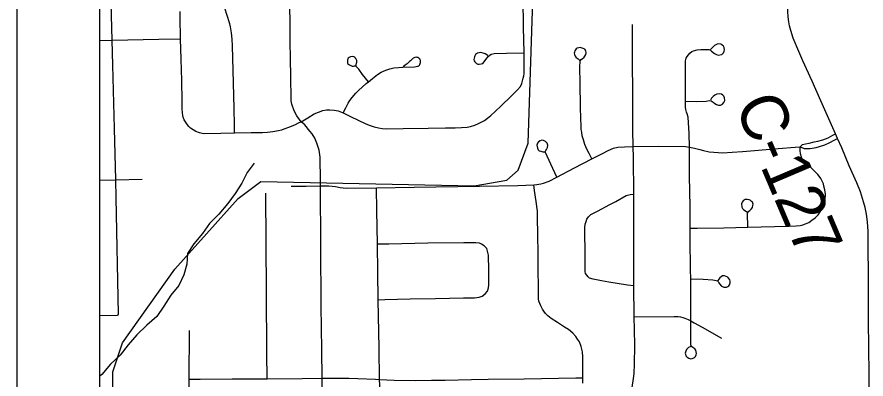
# Model space of a CAD drawing. Extents: x 0 to 34, y -5 to 22.
# Drawn here: x 2 to 3.028, y 19.297 to 19.735 of the extents above; entities that cross this region are included whole.
import ezdxf

# ---------------------------------------------------------------- set-up
doc = ezdxf.new("R2010")
doc.units = 0
for name, color, linetype in [('GM_X_City_Street', 7, 'Continuous'), ('GM_X_County_Road', 7, 'Continuous'), ('GM_X_County_Road_Text', 7, 'Continuous'), ('GM_X_Minor_River', 7, 'Continuous'), ('GM_X_Rail_Line', 7, 'Continuous'), ('GM_X_US_Route', 7, 'Continuous'), ('SH_Cut_Line', 7, 'Continuous'), ('SH_Data', 7, 'Continuous')]:
    doc.layers.add(name, color=color, linetype=linetype)

msp = doc.modelspace()

# ---------------------------------------------------------------- linework, layer by layer
at = {"layer": 'GM_X_City_Street'}
for points in [[(2.1227, 19.3747), (2.1231, 19.3759), (2.1202, 19.5161), (2.1196, 19.538), (2.1181, 19.6002), (2.1159, 19.6767), (2.1154, 19.7071), (2.1136, 19.7672), (2.1134, 19.7782), (2.1131, 19.7867), (2.1134, 19.7899), (2.1141, 19.7918), (2.1152, 19.7943), (2.1159, 19.7953), (2.1174, 19.7975), (2.1194, 19.7995), (2.1242, 19.8024), (2.1323, 19.8068), (2.1497, 19.8166), (2.1761, 19.8318), (2.1865, 19.8378)], [(2.2633, 19.5944), (2.2632, 19.6037), (2.2629, 19.6249), (2.2617, 19.6702), (2.2609, 19.7003), (2.2606, 19.7083), (2.2599, 19.7159), (2.2585, 19.7231), (2.2579, 19.7269), (2.2543, 19.7379), (2.2519, 19.7447), (2.2489, 19.7513), (2.245, 19.7588), (2.2427, 19.7622), (2.2401, 19.7664), (2.2343, 19.7743), (2.2273, 19.7834), (2.2232, 19.7885)], [(2.3698, 19.2697), (2.3695, 19.2977), (2.3692, 19.3323), (2.3685, 19.3853), (2.3676, 19.5307), (2.3674, 19.5367), (2.3671, 19.5654), (2.3659, 19.574), (2.3632, 19.5822), (2.3608, 19.5883), (2.3574, 19.5937), (2.3548, 19.5969), (2.3484, 19.6044), (2.344, 19.6083), (2.3388, 19.6153), (2.3356, 19.6213), (2.3329, 19.6295), (2.3322, 19.6336), (2.3319, 19.6376), (2.3316, 19.6609), (2.3313, 19.6864), (2.331, 19.7035), (2.3307, 19.7276), (2.3301, 19.7693)], [(2.344, 19.6083), (2.3432, 19.6078), (2.3405, 19.6064), (2.337, 19.6047), (2.3302, 19.6017), (2.3232, 19.5991), (2.3203, 19.5982), (2.3165, 19.5973), (2.3099, 19.5962), (2.3034, 19.5954), (2.2973, 19.595), (2.2834, 19.5948), (2.2633, 19.5944), (2.2467, 19.594), (2.2276, 19.5937), (2.2244, 19.5941), (2.221, 19.5948), (2.2166, 19.5964), (2.2133, 19.5983), (2.2101, 19.6007), (2.208, 19.6027), (2.2065, 19.6046), (2.2041, 19.608), (2.2026, 19.6106), (2.2013, 19.6139), (2.2007, 19.6159), (2.2003, 19.6189), (2.2002, 19.624), (2.1999, 19.6332), (2.1995, 19.6582), (2.1989, 19.6841), (2.1982, 19.7088), (2.1975, 19.7346), (2.1978, 19.7417)], [(2.344, 19.6083), (2.3523, 19.613), (2.3597, 19.6178), (2.365, 19.62), (2.3702, 19.6218), (2.375, 19.6225), (2.3789, 19.6228), (2.3839, 19.6223), (2.3891, 19.6213), (2.3951, 19.6189), (2.4039, 19.6148), (2.4223, 19.6059), (2.4278, 19.6036), (2.4324, 19.602), (2.4379, 19.6008), (2.4423, 19.6), (2.4474, 19.5998), (2.4677, 19.6001), (2.4981, 19.6006), (2.519, 19.6009), (2.5306, 19.6011), (2.5384, 19.6013), (2.5452, 19.6017), (2.5491, 19.6027), (2.5543, 19.6042), (2.559, 19.6061), (2.5631, 19.6081), (2.5663, 19.6099), (2.5698, 19.6125), (2.5737, 19.616), (2.5789, 19.6205), (2.5867, 19.628), (2.5979, 19.6388), (2.606, 19.6469), (2.6096, 19.6511), (2.6112, 19.6546), (2.6131, 19.6609), (2.6139, 19.6639), (2.6141, 19.6661), (2.6143, 19.6797), (2.6141, 19.6917), (2.6135, 19.7227), (2.6132, 19.7331), (2.613, 19.7468)], [(2.743, 19.0912), (2.7429, 19.1033), (2.7425, 19.1675), (2.7422, 19.2036), (2.742, 19.2373), (2.742, 19.2436), (2.7422, 19.2495), (2.7422, 19.2602), (2.7424, 19.2677), (2.7431, 19.2752), (2.7448, 19.2864), (2.7464, 19.2976), (2.7472, 19.3037), (2.7477, 19.3147), (2.7481, 19.3376), (2.7478, 19.3566), (2.7473, 19.3723), (2.747, 19.4098), (2.7468, 19.5125), (2.7469, 19.5207), (2.7466, 19.565), (2.7461, 19.5782), (2.7459, 19.5982), (2.7454, 19.7258)], [(2.1, 19.7068), (2.1154, 19.7071), (2.1719, 19.7083), (2.1982, 19.7088)], [(2.8158, 19.3364), (2.8132, 19.3349), (2.8121, 19.3338), (2.8108, 19.3324), (2.8098, 19.3305), (2.8093, 19.3282), (2.8094, 19.3268), (2.81, 19.325), (2.8114, 19.3233), (2.8134, 19.3221), (2.8159, 19.3214), (2.8176, 19.3216), (2.819, 19.3221), (2.8206, 19.323), (2.8217, 19.3243), (2.8224, 19.326), (2.8228, 19.3279), (2.8226, 19.3298), (2.8221, 19.3316), (2.821, 19.3332), (2.8197, 19.3342), (2.8183, 19.3352), (2.8168, 19.3363), (2.8162, 19.3371), (2.8159, 19.3382), (2.816, 19.3432), (2.8161, 19.3473), (2.8161, 19.3579), (2.816, 19.3672), (2.8158, 19.418), (2.8155, 19.4295), (2.8153, 19.4664), (2.8152, 19.4795), (2.815, 19.5051), (2.8144, 19.5428), (2.8142, 19.5776), (2.8139, 19.5941), (2.8129, 19.6137), (2.8114, 19.6178), (2.8108, 19.6199), (2.8099, 19.6229), (2.8095, 19.6259), (2.8095, 19.633), (2.8094, 19.6729), (2.8095, 19.6822), (2.8104, 19.6854), (2.8114, 19.6873), (2.8131, 19.6894), (2.8147, 19.6912), (2.8173, 19.6933), (2.8192, 19.6943), (2.8236, 19.6954), (2.8282, 19.6956), (2.8378, 19.6956), (2.8397, 19.6949), (2.8411, 19.6938), (2.8445, 19.691), (2.8469, 19.6897), (2.8491, 19.6888), (2.8535, 19.6896), (2.8555, 19.6917), (2.8565, 19.6936), (2.8566, 19.6955), (2.8564, 19.698), (2.8554, 19.6997), (2.8536, 19.7014), (2.8522, 19.7022), (2.8498, 19.7027), (2.8478, 19.7023), (2.8461, 19.7015), (2.8446, 19.7005), (2.8435, 19.6995), (2.8418, 19.6978), (2.84, 19.6956)], [(2.57, 19.6883), (2.5668, 19.6903), (2.5644, 19.6912), (2.5616, 19.6919), (2.5578, 19.6913), (2.5563, 19.6905), (2.5553, 19.6895), (2.5545, 19.6881), (2.554, 19.6869), (2.5535, 19.6854), (2.5533, 19.6837), (2.5537, 19.6821), (2.5545, 19.6809), (2.5555, 19.6796), (2.5563, 19.6786), (2.5582, 19.6781), (2.5598, 19.6778), (2.5622, 19.6782), (2.564, 19.6789), (2.5657, 19.6806), (2.5678, 19.6836), (2.5709, 19.6878), (2.5742, 19.6899), (2.5778, 19.6908), (2.5926, 19.6913), (2.6141, 19.6917)], [(2.696, 19.5632), (2.6927, 19.5697), (2.6901, 19.575), (2.6877, 19.5806), (2.686, 19.5862), (2.6846, 19.5912), (2.6838, 19.5956), (2.6833, 19.599), (2.683, 19.6035), (2.6826, 19.6124), (2.6823, 19.626), (2.682, 19.6552), (2.6817, 19.6739), (2.6819, 19.6822), (2.6833, 19.6836), (2.6849, 19.6847), (2.6863, 19.6858), (2.6878, 19.6878), (2.6887, 19.6898), (2.6891, 19.6915), (2.6887, 19.694), (2.6883, 19.6948), (2.6877, 19.696), (2.6858, 19.6971), (2.683, 19.6979), (2.6818, 19.6981), (2.6802, 19.6979), (2.6784, 19.6972), (2.6773, 19.6965), (2.6763, 19.6954), (2.6755, 19.6941), (2.675, 19.6926), (2.6747, 19.6913), (2.675, 19.6896), (2.6754, 19.6886), (2.6759, 19.6876), (2.6766, 19.6866), (2.6773, 19.6859), (2.6782, 19.6852), (2.6794, 19.6843), (2.6815, 19.6826)], [(2.3951, 19.6189), (2.3982, 19.6253), (2.401, 19.6308), (2.403, 19.6339), (2.4057, 19.6377), (2.4103, 19.643), (2.4134, 19.6462), (2.4229, 19.6544), (2.4258, 19.6566), (2.4307, 19.6606), (2.4365, 19.6653), (2.4411, 19.6682), (2.4465, 19.6708), (2.4513, 19.6725), (2.4564, 19.6736), (2.462, 19.674), (2.4673, 19.6742), (2.4815, 19.6748), (2.4833, 19.675), (2.4851, 19.6754), (2.4859, 19.6757), (2.4866, 19.6761), (2.4871, 19.6764), (2.4874, 19.6768), (2.4877, 19.6774), (2.4884, 19.6786), (2.4887, 19.6799), (2.4888, 19.6813), (2.4887, 19.6823), (2.4884, 19.6832), (2.4881, 19.6839), (2.4875, 19.6846), (2.4866, 19.6854), (2.4855, 19.686), (2.4845, 19.6862), (2.4833, 19.6864), (2.4818, 19.6862), (2.4809, 19.6858), (2.4799, 19.6852), (2.4789, 19.6843), (2.4781, 19.6835), (2.4767, 19.6822), (2.4753, 19.681), (2.4741, 19.6799), (2.4725, 19.6785), (2.47, 19.6766), (2.4677, 19.6747)], [(2.4258, 19.6566), (2.4186, 19.6656), (2.4138, 19.6719), (2.4112, 19.6748), (2.4107, 19.676), (2.4108, 19.677), (2.4111, 19.6791), (2.4114, 19.6804), (2.4114, 19.6823), (2.4111, 19.6831), (2.4109, 19.6837), (2.4105, 19.6849), (2.4092, 19.6862), (2.408, 19.6868), (2.4067, 19.6873), (2.4037, 19.687), (2.4021, 19.6862), (2.4011, 19.6852), (2.4005, 19.6842), (2.4003, 19.6832), (2.4002, 19.6823), (2.4001, 19.6815), (2.4003, 19.6795), (2.4008, 19.6785), (2.4017, 19.6776), (2.4028, 19.677), (2.4041, 19.6763), (2.4059, 19.6757), (2.4074, 19.6757), (2.4087, 19.6758), (2.4103, 19.676)], [(2.8095, 19.633), (2.8231, 19.6328), (2.8345, 19.6332), (2.8381, 19.634), (2.8405, 19.6335), (2.8429, 19.632), (2.845, 19.6305), (2.847, 19.6291), (2.8494, 19.6283), (2.852, 19.6285), (2.8544, 19.6295), (2.8561, 19.6316), (2.857, 19.634), (2.8567, 19.6374), (2.8559, 19.6391), (2.8546, 19.6406), (2.8531, 19.6415), (2.8508, 19.642), (2.8473, 19.6415), (2.8452, 19.6405), (2.8429, 19.6388), (2.841, 19.6368), (2.8398, 19.6344)], [(2.6536, 19.541), (2.6489, 19.5518), (2.6419, 19.5665), (2.6397, 19.5718), (2.6403, 19.5733), (2.6413, 19.5746), (2.6424, 19.577), (2.643, 19.58), (2.642, 19.5825), (2.64, 19.5844), (2.6376, 19.5854), (2.6357, 19.5858), (2.6337, 19.5853), (2.6317, 19.5839), (2.6304, 19.5822), (2.6297, 19.58), (2.6302, 19.5761), (2.6312, 19.5741), (2.6325, 19.5732), (2.6343, 19.5725), (2.6366, 19.572), (2.6391, 19.5718)], [(2.9482, 19.5781), (2.9513, 19.5806), (2.9547, 19.5816), (2.9594, 19.5824), (2.9655, 19.5838), (2.9696, 19.5848), (2.976, 19.5865), (2.9822, 19.5889), (2.9879, 19.592), (2.9913, 19.5938)], [(2.9482, 19.5781), (2.9533, 19.576), (2.9563, 19.5757), (2.9606, 19.576), (2.9677, 19.5772), (2.9718, 19.5782), (2.9781, 19.5805), (2.9834, 19.5827), (2.9903, 19.5864), (2.9937, 19.588)], [(2.332, 19.5301), (2.3503, 19.5304), (2.3676, 19.5307), (2.3776, 19.5308), (2.3856, 19.53), (2.3915, 19.5286), (2.3986, 19.5279), (2.4353, 19.5282), (2.4811, 19.529), (2.5601, 19.5304), (2.6065, 19.5312), (2.6259, 19.5319), (2.6296, 19.5323), (2.6343, 19.5332), (2.6375, 19.5339), (2.6446, 19.5364), (2.6536, 19.541), (2.6752, 19.5525), (2.696, 19.5632), (2.7089, 19.5699), (2.716, 19.5735), (2.7224, 19.5762), (2.7276, 19.5773), (2.7356, 19.5781), (2.7461, 19.5782), (2.7768, 19.5786), (2.8096, 19.5783), (2.8142, 19.5776), (2.8203, 19.5764), (2.8269, 19.5747), (2.8314, 19.5736), (2.8381, 19.572), (2.844, 19.5714), (2.8542, 19.5708), (2.8662, 19.5714), (2.8786, 19.5722), (2.9218, 19.5759), (2.9424, 19.5776), (2.9482, 19.5781)], [(2.8152, 19.4795), (2.8237, 19.4796), (2.8561, 19.4798), (2.8849, 19.4806), (2.9173, 19.4814), (2.9352, 19.4818), (2.9436, 19.4822), (2.9485, 19.4828), (2.9515, 19.4836), (2.955, 19.4848), (2.9587, 19.4864), (2.9626, 19.489), (2.9667, 19.4921), (2.97, 19.4955), (2.9727, 19.4992), (2.9753, 19.5037), (2.9763, 19.5069), (2.9774, 19.5108), (2.9781, 19.5135), (2.9786, 19.5157), (2.9789, 19.5181), (2.9789, 19.5207), (2.9784, 19.5257), (2.9772, 19.5302), (2.9765, 19.5331), (2.975, 19.5365), (2.9733, 19.5394), (2.9725, 19.5406), (2.9699, 19.5444), (2.9665, 19.5478), (2.9626, 19.5515), (2.959, 19.5549), (2.9555, 19.5582), (2.9538, 19.5601), (2.9514, 19.5626), (2.95, 19.5655), (2.9489, 19.5693), (2.9482, 19.5734), (2.9482, 19.5781)], [(2.1, 19.5377), (2.1196, 19.538), (2.1516, 19.5386)], [(2.4429, 19.0853), (2.4413, 19.1791), (2.4403, 19.2379), (2.4396, 19.2825), (2.439, 19.2963), (2.4385, 19.3342), (2.4375, 19.3929), (2.4369, 19.4262), (2.4364, 19.4599), (2.4358, 19.5007), (2.4353, 19.5282)], [(2.6854, 19.2919), (2.6854, 19.2982), (2.6852, 19.3239), (2.6849, 19.3299), (2.6832, 19.3364), (2.681, 19.3418), (2.6789, 19.3452), (2.6766, 19.3485), (2.673, 19.3525), (2.6677, 19.3566), (2.6631, 19.3597), (2.6547, 19.3652), (2.647, 19.3703), (2.6429, 19.3733), (2.6399, 19.3763), (2.6378, 19.3791), (2.6363, 19.3813), (2.6343, 19.3854), (2.6331, 19.3883), (2.6321, 19.3912), (2.6315, 19.394), (2.6314, 19.409), (2.6313, 19.4281), (2.6311, 19.4494), (2.6309, 19.4707), (2.6305, 19.4934), (2.6302, 19.5002), (2.6287, 19.5117), (2.6267, 19.5252), (2.6259, 19.5319)], [(2.3029, 19.2972), (2.3026, 19.3283), (2.3021, 19.4021), (2.3012, 19.5217)], [(2.747, 19.4098), (2.7391, 19.4104), (2.7167, 19.4142), (2.7079, 19.4157), (2.6978, 19.4176), (2.6934, 19.4188), (2.6918, 19.4204), (2.6899, 19.4224), (2.6886, 19.4246), (2.688, 19.4268), (2.6879, 19.4547), (2.6878, 19.4699), (2.6877, 19.4799), (2.688, 19.4841), (2.6891, 19.4877), (2.6902, 19.4903), (2.6921, 19.493), (2.6949, 19.4959), (2.7029, 19.5), (2.718, 19.508), (2.725, 19.5116), (2.7378, 19.5188), (2.7425, 19.5204), (2.7469, 19.5207)], [(2.8849, 19.4806), (2.8847, 19.4973), (2.8852, 19.4986), (2.8862, 19.5), (2.8875, 19.501), (2.8892, 19.5026), (2.8907, 19.5043), (2.8912, 19.5067), (2.8913, 19.5084), (2.8905, 19.5108), (2.8895, 19.5119), (2.8878, 19.5132), (2.8865, 19.5137), (2.8844, 19.5142), (2.8819, 19.5141), (2.8805, 19.5134), (2.8792, 19.5124), (2.8783, 19.5108), (2.8774, 19.5091), (2.8777, 19.505), (2.8786, 19.5032), (2.8797, 19.502), (2.8812, 19.5008), (2.8846, 19.4988)], [(2.4375, 19.3929), (2.4456, 19.3931), (2.4761, 19.3941), (2.5066, 19.3944), (2.5409, 19.395), (2.5542, 19.3952), (2.5596, 19.3958), (2.5635, 19.3972), (2.5669, 19.3999), (2.5697, 19.4031), (2.5711, 19.4074), (2.5714, 19.4109), (2.5712, 19.4285), (2.5709, 19.4469), (2.5688, 19.4549), (2.5659, 19.458), (2.5624, 19.4601), (2.5599, 19.4612), (2.5556, 19.4616), (2.541, 19.4615), (2.4976, 19.4611), (2.4501, 19.4602), (2.4364, 19.4599)], [(2.8158, 19.418), (2.8309, 19.4179), (2.8426, 19.4168), (2.8468, 19.4162), (2.8483, 19.4159), (2.8491, 19.4148), (2.85, 19.4134), (2.8507, 19.4119), (2.853, 19.4094), (2.8561, 19.4079), (2.859, 19.408), (2.8608, 19.4088), (2.8622, 19.4098), (2.8629, 19.4109), (2.8636, 19.4133), (2.8636, 19.4153), (2.8631, 19.4169), (2.8622, 19.4186), (2.8606, 19.4201), (2.8589, 19.421), (2.8566, 19.4217), (2.8542, 19.4216), (2.8527, 19.4207), (2.8512, 19.4193), (2.8487, 19.4163)], [(2.1, 19.3739), (2.1218, 19.3742), (2.1227, 19.3747)], [(2.7473, 19.3723), (2.7957, 19.3727), (2.8007, 19.3725), (2.8036, 19.3722), (2.8062, 19.3715), (2.8089, 19.3706), (2.8126, 19.369), (2.816, 19.3672), (2.82, 19.365), (2.8297, 19.3596), (2.8532, 19.3463)], [(2.2099, 19.0804), (2.2098, 19.1636), (2.2094, 19.2062), (2.2091, 19.23), (2.2089, 19.2442), (2.2088, 19.2575), (2.2085, 19.2789), (2.2084, 19.2966), (2.209, 19.3554)], [(2.2084, 19.2966), (2.2218, 19.2967), (2.2604, 19.2972), (2.3029, 19.2972), (2.3452, 19.2976), (2.3695, 19.2977), (2.3902, 19.298), (2.4019, 19.2979), (2.4129, 19.2975), (2.4343, 19.2966), (2.439, 19.2963), (2.4566, 19.2954), (2.4831, 19.295), (2.502, 19.2954), (2.5185, 19.2956), (2.5504, 19.2962), (2.5705, 19.2965), (2.614, 19.2972), (2.6769, 19.2982), (2.6854, 19.2982)]]:
    msp.add_lwpolyline(points, dxfattribs=at)
at = {"layer": 'GM_X_County_Road'}
for points in [[(2.9468, 19.6932), (2.94, 19.7095), (2.9369, 19.7187), (2.9355, 19.7244), (2.9345, 19.7294), (2.9337, 19.7353), (2.933, 19.7483)], [(2.9736, 19.6334), (2.9628, 19.6572), (2.9518, 19.6819), (2.9468, 19.6932)], [(3.0251, 19.5114), (3.0213, 19.5233), (3.017, 19.5343), (3.0079, 19.5549), (2.9987, 19.5765), (2.9937, 19.588), (2.9913, 19.5938), (2.9815, 19.6155), (2.9736, 19.6334)], [(3.0332, 19.0954), (3.033, 19.1116), (3.0327, 19.1905), (3.0326, 19.2185), (3.0328, 19.2411), (3.0321, 19.3027), (3.0313, 19.3672), (3.0311, 19.3993), (3.0311, 19.4041), (3.0309, 19.4754), (3.0299, 19.4872), (3.0286, 19.4962), (3.027, 19.5043), (3.0251, 19.5114)]]:
    msp.add_lwpolyline(points, dxfattribs=at)
at = {"layer": 'GM_X_Minor_River'}
msp.add_lwpolyline([(2.2873, 19.558), (2.2786, 19.5469), (2.2723, 19.5339), (2.2641, 19.5216), (2.2555, 19.5093), (2.2446, 19.4966), (2.2333, 19.4851), (2.2247, 19.4728), (2.2142, 19.4605), (2.2064, 19.4486), (2.2058, 19.4357), (2.2021, 19.4231), (2.1958, 19.4101), (2.1864, 19.3982), (2.1778, 19.3851), (2.1692, 19.3725), (2.1572, 19.3621), (2.1451, 19.3505), (2.1346, 19.3382), (2.1249, 19.3256), (2.1132, 19.3148), (2.1027, 19.3025), (2.1, 19.3001)], dxfattribs=at)
at = {"layer": 'GM_X_Rail_Line'}
msp.add_lwpolyline([(2.2641, 18.6409), (2.2591, 18.6644), (2.2611, 18.7131), (2.2691, 18.7598), (2.2758, 18.8222), (2.2728, 18.8936), (2.2607, 18.9498), (2.2425, 18.9954), (2.204, 19.0606), (2.16, 19.1448), (2.1159, 19.2624), (2.1159, 19.2791), (2.1159, 19.3055), (2.1276, 19.3408), (2.1913, 19.43), (2.2677, 19.5152), (2.2951, 19.5358), (2.5538, 19.5308), (2.5933, 19.5377), (2.607, 19.5497), (2.619, 19.5823), (2.6346, 20.0632)], dxfattribs=at)
at = {"layer": 'GM_X_US_Route'}
msp.add_lwpolyline([(4.0056, 17.7327), (4.0095, 18.3868), (4.0098, 19.1097), (4.005, 19.9814), (4.0049, 20.0266), (4.0047, 20.1034), (4.0052, 20.1906), (4.0053, 20.2144), (4.0055, 20.2299), (4.0039, 20.4099), (4.0031, 20.5369), (4.0016, 20.728), (4.0011, 20.7857), (4.0002, 20.8844), (4.0002, 20.9), (2.1, 20.9), (2.1, 16.5221)], dxfattribs=at)
at = {"layer": 'SH_Cut_Line'}
msp.add_lwpolyline([(4.0056, 17.7327), (4.0095, 18.3868), (4.0098, 19.1097), (4.005, 19.9814), (4.0049, 20.0266), (4.0047, 20.1034), (4.0052, 20.1906), (4.0053, 20.2144), (4.0055, 20.2299), (4.0039, 20.4099), (4.0031, 20.5369), (4.0016, 20.728), (4.0011, 20.7857), (4.0002, 20.8844), (4.0002, 20.9), (2.1, 20.9), (2.1, 16.5221)], dxfattribs=at)
at = {"layer": 'SH_Data'}
for p, q in [((2, 21), (2, 14)), ((2.1, 20.9), (2.1, 14.1))]:
    msp.add_line(p, q, dxfattribs=at)

# ---------------------------------------------------------------- texts
at = {"layer": 'GM_X_County_Road_Text'}
msp.add_text('C-127', height=0.05682, rotation=293.0188, dxfattribs=at).set_placement((2.8684, 19.6287))

doc.saveas('drawing.dxf')
